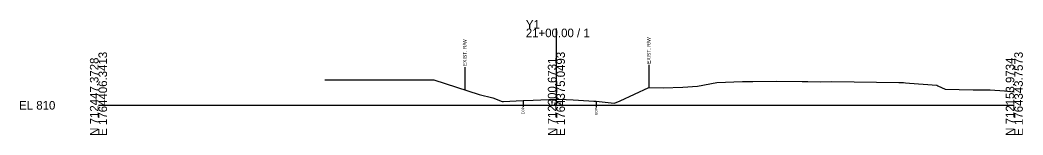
# Model space of a CAD drawing. Extents: x -26 to 1303, y -10 to 9524.
# Drawn here: x 974.3 to 1302.8, y 990.3 to 1027.9 of the extents above; entities that cross this region are included whole.
import ezdxf

# ---------------------------------------------------------------- set-up
doc = ezdxf.new("R2010")
doc.units = 0
for name, color, linetype in [('Default', 7, 'Continuous'), ('Exist Cross Section Cell', 7, 'Continuous'), ('Exist XS Center Line Elevation Label', 7, 'Continuous'), ('Exist XS Ground Line', 7, 'Continuous'), ('Old_Level_10', 7, 'Continuous')]:
    doc.layers.add(name, color=color, linetype=linetype)

msp = doc.modelspace()

# ---------------------------------------------------------------- linework, layer by layer
at = {"layer": 'Exist Cross Section Cell'}
for p, q in [((1150, 1000), (1150, 1025.07)), ((1000, 1000), (1150, 1000)), ((1150, 1000), (1300, 1000))]:
    msp.add_line(p, q, dxfattribs=at)
at = {"layer": 'Exist XS Ground Line'}
msp.add_lwpolyline([(1074.11, 1008.36), (1078.34, 1008.3), (1085.98, 1008.29), (1109.9, 1008.34), (1124.7, 1003.56), (1129.19, 1002.47), (1132.24, 1001.22), (1132.67, 1001.23), (1136.87, 1001.47), (1139.07, 1001.53), (1142.36, 1001.68), (1150, 1002.01), (1150.91, 1002.05), (1155.49, 1001.75), (1160.59, 1001.42), (1162.22, 1001.37), (1163.03, 1001.34), (1167.94, 1000.77), (1169.01, 1000.7), (1170.85, 1001.5), (1180.32, 1005.81), (1185.01, 1005.66), (1191.46, 1005.95), (1196.18, 1006.3), (1202.57, 1007.48), (1211.02, 1007.73), (1214.31, 1007.78), (1222.14, 1007.9), (1230.54, 1007.82), (1232.37, 1007.82), (1236.55, 1007.71), (1240.22, 1007.73), (1262.15, 1007.46), (1263.03, 1007.41), (1263.72, 1007.4), (1264.39, 1007.34), (1265.66, 1007.25), (1274.61, 1006.54), (1274.93, 1006.41), (1277.38, 1005.32), (1286.52, 1005.07), (1292.14, 1005.1), (1296.76, 1004.74), (1300, 1004.38)], dxfattribs=at)
at = {"layer": 'Old_Level_10'}
for p, q in [((1120, 1012.48), (1120, 1005.08)), ((1180.25, 1013.18), (1180.25, 1005.78)), ((1139.07, 1001.53), (1139.07, 999.47)), ((1163.03, 1001.34), (1163.03, 999.29))]:
    msp.add_line(p, q, dxfattribs=at)

# ---------------------------------------------------------------- texts
at = {"layer": 'Default'}
msp.add_text('-', height=0.0001, dxfattribs=at).set_placement((1000, 1000))
at = {"layer": 'Exist Cross Section Cell'}
for s, p in [('Y1', (1140, 1025.07)), ('21+00.00 / 1', (1140, 1022.27)), ('EL 810', (974, 998.6))]:
    msp.add_text(s, height=2.8, dxfattribs=at).set_placement(p)
for s, p in [('N 712447.3728', (1000, 990)), ('E 1764406.3413', (1002.8, 990)), ('N 712300.6731', (1150, 990)), ('E 1764375.0493', (1152.8, 990)), ('N 712153.9734', (1300, 990)), ('E 1764343.7573', (1302.8, 990))]:
    msp.add_text(s, height=2.8, rotation=90, dxfattribs=at).set_placement(p)
at = {"layer": 'Exist XS Center Line Elevation Label'}
msp.add_text('812.01', height=1, dxfattribs=at).set_placement((1148.16, 1000.01))
at = {"layer": 'Old_Level_10'}
for s, height, p in [('EXIST. R/W', 1.181, (1180.84, 1013.48)), ('EXIST. R/W', 1.181, (1120.59, 1012.78)), ('EOP', 0.787, (1139.46, 997.08)), ('EOP', 0.787, (1163.42, 996.89))]:
    msp.add_text(s, height=height, rotation=90, dxfattribs=at).set_placement(p)

doc.saveas('drawing.dxf')
